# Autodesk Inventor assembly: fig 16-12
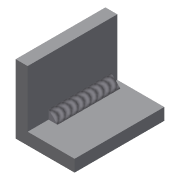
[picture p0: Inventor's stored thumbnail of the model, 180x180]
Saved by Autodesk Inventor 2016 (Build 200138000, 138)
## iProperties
Created: 2009-05
Part Number: fig 16-12
Document SubType Name: Weldment
Designer: Sham
Weld Material: Welded Aluminum-6061
Author: Sham
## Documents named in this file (2)
- D:\KAVITA\Autodesk Inventor_ 2016 Project_Kavita\Inventor_Part Files\Inventor_2016_Part\c16_Inv_2016\c16_inv_2016_prt\fig 16-12.iam
- D:\KAVITA\Autodesk Inventor_ 2016 Project_Kavita\Inventor_Part Files\Inventor_2016_Part\c16_Inv_2016\c16_inv_2016_prt\Part3.ipt
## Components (1 placed, 1 different names)
1. Part3:1
